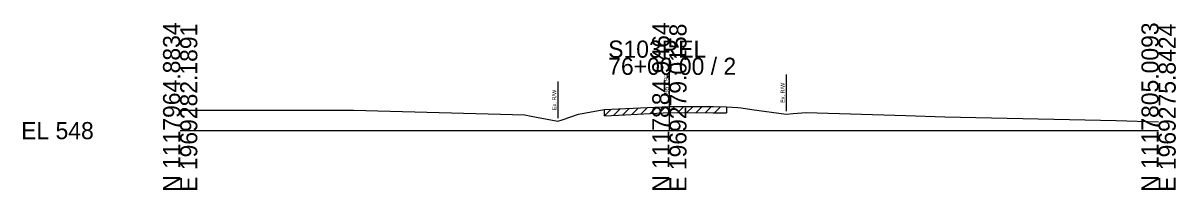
# Model space of a CAD drawing. Extents: x -26 to 163, y -10 to 24518.
# Drawn here: x -25.7 to 162.8, y 24490.3 to 24517.6 of the extents above; entities that cross this region are included whole.
import ezdxf

# ---------------------------------------------------------------- set-up
doc = ezdxf.new("R2010")
doc.units = 0
for name, color, linetype in [('RD_GPK_XS_Cell', 7, 'Continuous'), ('RD_XS_ExGround', 7, 'Continuous'), ('RD_XS_ExPaveRet', 7, 'Continuous'), ('RD_XS_ExRW', 7, 'Continuous'), ('RD_XS_TX_Elev_EX', 7, 'Continuous')]:
    doc.layers.add(name, color=color, linetype=linetype)

msp = doc.modelspace()

# ---------------------------------------------------------------- linework, layer by layer
at = {"layer": 'RD_GPK_XS_Cell'}
for p, q in [((80, 24500), (80, 24511.92)), ((0, 24500), (80, 24500)), ((80, 24500), (160, 24500))]:
    msp.add_line(p, q, dxfattribs=at)
at = {"layer": 'RD_XS_ExGround'}
msp.add_lwpolyline([(0, 24503.37), (27.98, 24503.36), (28.34, 24503.35), (56.38, 24502.57), (57.39, 24502.37), (61.75, 24501.53), (62.48, 24501.79), (65.16, 24502.71), (68.41, 24503.27), (69.38, 24503.43), (71.69, 24503.54), (80.03, 24503.97), (87.17, 24503.92), (89.36, 24503.9), (91.21, 24503.76), (91.76, 24503.72), (93.5, 24503.48), (99.11, 24502.68), (100.23, 24502.78), (102.39, 24502.97), (118.65, 24502.48), (125.05, 24502.28), (153.05, 24501.65), (160, 24501.46)], dxfattribs=at)
at = {"layer": 'RD_XS_ExPaveRet'}
for p, q in [((72.38, 24502.57), (73.43, 24503.63)), ((73.88, 24502.65), (74.93, 24503.71)), ((75.38, 24502.73), (76.43, 24503.79)), ((76.88, 24502.81), (77.93, 24503.86)), ((78.38, 24502.89), (79.43, 24503.94)), ((79.88, 24502.97), (80.88, 24503.97)), ((81.38, 24502.96), (82.37, 24503.96)), ((82.88, 24502.95), (83.87, 24503.95)), ((84.38, 24502.94), (85.37, 24503.94)), ((85.88, 24502.93), (86.87, 24503.93)), ((87.38, 24502.92), (88.37, 24503.91)), ((89.36, 24503.9), (89.36, 24502.9)), ((69.38, 24502.43), (70.43, 24503.48)), ((69.38, 24502.43), (69.38, 24503.43)), ((69.38, 24502.43), (71.69, 24502.54)), ((70.88, 24502.5), (71.93, 24503.55)), ((71.69, 24502.54), (80.03, 24502.97)), ((80.03, 24502.97), (87.17, 24502.92)), ((87.17, 24502.92), (89.36, 24502.9))]:
    msp.add_line(p, q, dxfattribs=at)
at = {"layer": 'RD_XS_ExRW'}
for p, q in [((61.75, 24508.03), (61.75, 24502.03)), ((99.11, 24509.18), (99.11, 24503.18))]:
    msp.add_line(p, q, dxfattribs=at)

# ---------------------------------------------------------------- texts
at = {"layer": 'RD_GPK_XS_Cell'}
for s, p in [('N 1117964.8834', (0, 24490)), ('E 1969282.1891', (2.8, 24490)), ('N 1117884.9464', (80, 24490)), ('E 1969279.0158', (82.8, 24490)), ('N 1117805.0093', (160, 24490)), ('E 1969275.8424', (162.8, 24490))]:
    msp.add_text(s, height=2.8, rotation=90, dxfattribs=at).set_placement(p)
for s, p in [('S103REL', (70, 24511.92)), ('76+00.00 / 2', (70, 24509.12)), ('EL 548', (-26, 24498.6))]:
    msp.add_text(s, height=2.8, dxfattribs=at).set_placement(p)
at = {"layer": 'RD_XS_ExRW'}
for p in [(98.86, 24504.53), (61.5, 24503.38)]:
    msp.add_text('Ex. R/W ', height=0.65, rotation=90, dxfattribs=at).set_placement(p)
at = {"layer": 'RD_XS_TX_Elev_EX'}
msp.add_text('551.97', height=0.8, rotation=90, dxfattribs=at).set_placement((79.9, 24505.97))

doc.saveas('drawing.dxf')
